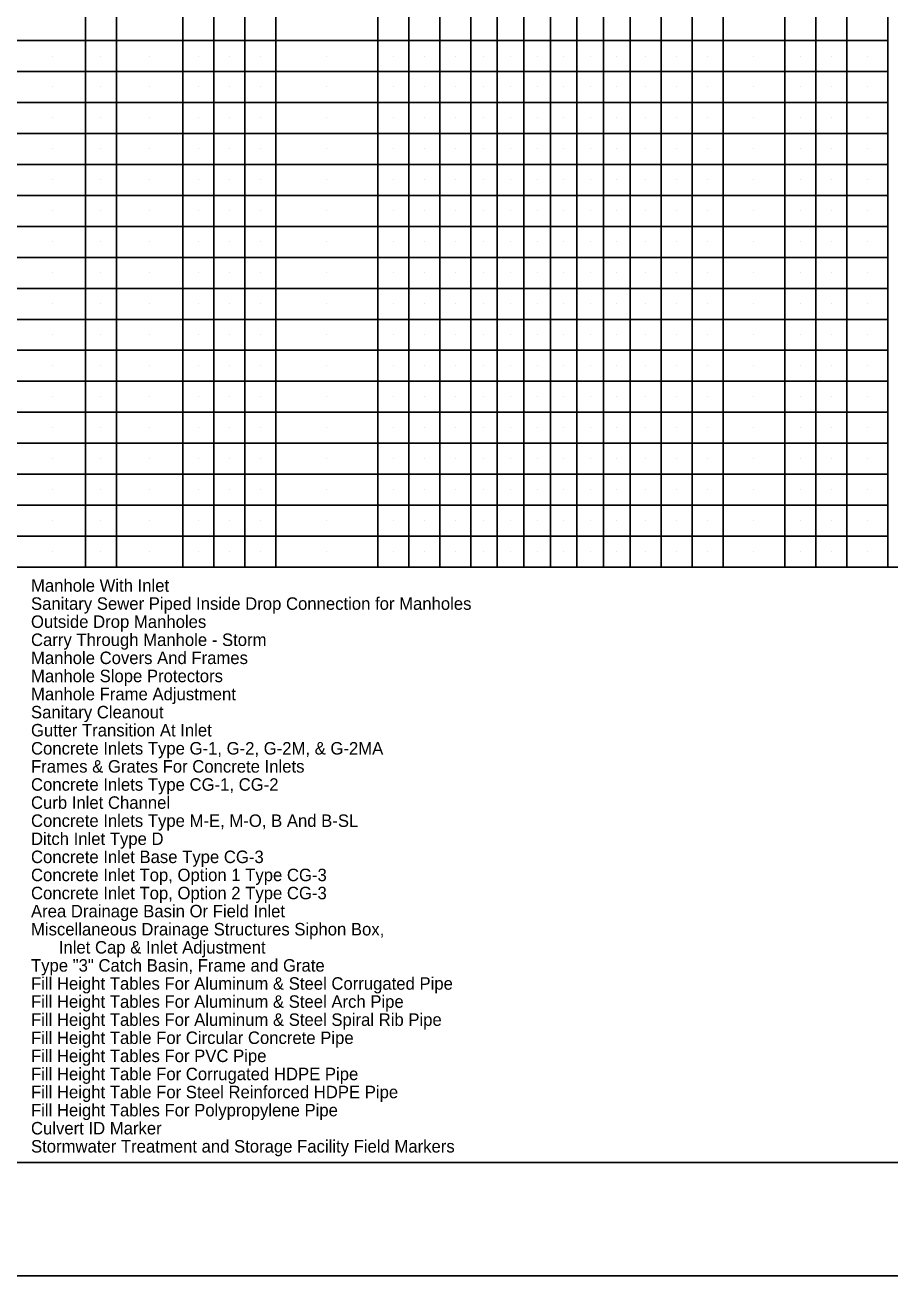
# Model space of a CAD drawing. Extents: x -1700 to 0, y 0 to 1100.
# Drawn here: x -773 to -392, y 0 to 551 of the extents above; entities that cross this region are included whole.
import ezdxf

# ---------------------------------------------------------------- set-up
doc = ezdxf.new("R2010")
doc.units = 0
for name, color, linetype in [('#plot_shape', 7, 'Continuous'), ('P_ODOT_PLAN_Border', 7, 'Continuous'), ('P_ODOT_PLAN_General', 7, 'Continuous'), ('P_RDWY_PLAN_NotesTx', 7, 'Continuous')]:
    doc.layers.add(name, color=color, linetype=linetype)

msp = doc.modelspace()

# ---------------------------------------------------------------- linework, layer by layer
at = {"layer": '#plot_shape'}
msp.add_lwpolyline([(-1700, 0), (0, 0), (0, 1100), (-1700, 1100)], close=True, dxfattribs=at)
at = {"layer": 'P_ODOT_PLAN_Border'}
msp.add_lwpolyline([(-1625, 50), (-25, 50), (-25, 1050), (-1625, 1050)], close=True, dxfattribs=at)
at = {"layer": 'P_ODOT_PLAN_General'}
for p, q in [((-392.85, 312.45), (-392.85, 1050)), ((-576.71, 312.45), (-576.71, 1036.34)), ((-506.47, 312.45), (-506.47, 1036.34)), ((-492.81, 312.45), (-492.81, 1023.66)), ((-479.15, 312.45), (-479.15, 1023.66)), ((-465.49, 312.45), (-465.49, 1023.66)), ((-438.17, 312.45), (-438.17, 1023.66)), ((-424.51, 312.45), (-424.51, 1023.66)), ((-410.85, 312.45), (-410.85, 1023.66)), ((-541.59, 312.45), (-541.59, 1010.98)), ((-662.68, 312.45), (-662.68, 998.29)), ((-565, 312.45), (-565, 998.29)), ((-553.3, 312.45), (-553.3, 998.29)), ((-529.88, 312.45), (-529.88, 998.29)), ((-518.17, 312.45), (-518.17, 998.29)), ((-732.93, 312.45), (-732.93, 985.61)), ((-690, 312.45), (-690, 985.61)), ((-617.68, 312.45), (-617.68, 985.61)), ((-604.03, 312.45), (-604.03, 985.61)), ((-746.59, 312.45), (-746.59, 973.9)), ((-703.66, 312.45), (-703.66, 973.9)), ((-676.34, 312.45), (-676.34, 973.9)), ((-590.37, 312.45), (-590.37, 973.9)), ((-392.85, 544.64), (-1033.79, 544.64)), ((-761.22, 537.81), (-761.22, 537.81)), ((-739.76, 537.81), (-739.76, 537.81)), ((-718.29, 537.81), (-718.29, 537.81)), ((-696.83, 537.81), (-696.83, 537.81)), ((-683.17, 537.81), (-683.17, 537.81)), ((-669.51, 537.81), (-669.51, 537.81)), ((-640.18, 537.81), (-640.18, 537.81)), ((-610.86, 537.81), (-610.86, 537.81)), ((-597.2, 537.81), (-597.2, 537.81)), ((-583.54, 537.81), (-583.54, 537.81)), ((-570.86, 537.81), (-570.86, 537.81)), ((-559.15, 537.81), (-559.15, 537.81)), ((-547.44, 537.81), (-547.44, 537.81)), ((-535.73, 537.81), (-535.73, 537.81)), ((-524.03, 537.81), (-524.03, 537.81)), ((-512.32, 537.81), (-512.32, 537.81)), ((-499.64, 537.81), (-499.64, 537.81)), ((-485.98, 537.81), (-485.98, 537.81)), ((-472.32, 537.81), (-472.32, 537.81)), ((-451.83, 537.81), (-451.83, 537.81)), ((-431.34, 537.81), (-431.34, 537.81)), ((-417.68, 537.81), (-417.68, 537.81)), ((-401.85, 537.81), (-401.85, 537.81)), ((-392.85, 530.98), (-1033.79, 530.98)), ((-761.22, 524.15), (-761.22, 524.15)), ((-739.76, 524.15), (-739.76, 524.15)), ((-718.29, 524.15), (-718.29, 524.15)), ((-696.83, 524.15), (-696.83, 524.15)), ((-683.17, 524.15), (-683.17, 524.15)), ((-669.51, 524.15), (-669.51, 524.15)), ((-640.18, 524.15), (-640.18, 524.15)), ((-610.86, 524.15), (-610.86, 524.15)), ((-597.2, 524.15), (-597.2, 524.15)), ((-583.54, 524.15), (-583.54, 524.15)), ((-570.86, 524.15), (-570.86, 524.15)), ((-559.15, 524.15), (-559.15, 524.15)), ((-547.44, 524.15), (-547.44, 524.15)), ((-535.73, 524.15), (-535.73, 524.15)), ((-524.03, 524.15), (-524.03, 524.15)), ((-512.32, 524.15), (-512.32, 524.15)), ((-499.64, 524.15), (-499.64, 524.15)), ((-485.98, 524.15), (-485.98, 524.15)), ((-472.32, 524.15), (-472.32, 524.15)), ((-451.83, 524.15), (-451.83, 524.15)), ((-431.34, 524.15), (-431.34, 524.15)), ((-417.68, 524.15), (-417.68, 524.15)), ((-401.85, 524.15), (-401.85, 524.15)), ((-392.85, 517.32), (-1033.79, 517.32)), ((-761.22, 510.49), (-761.22, 510.49)), ((-739.76, 510.49), (-739.76, 510.49)), ((-718.29, 510.49), (-718.29, 510.49)), ((-696.83, 510.49), (-696.83, 510.49)), ((-683.17, 510.49), (-683.17, 510.49)), ((-669.51, 510.49), (-669.51, 510.49)), ((-640.18, 510.49), (-640.18, 510.49)), ((-610.86, 510.49), (-610.86, 510.49)), ((-597.2, 510.49), (-597.2, 510.49)), ((-583.54, 510.49), (-583.54, 510.49)), ((-570.86, 510.49), (-570.86, 510.49)), ((-559.15, 510.49), (-559.15, 510.49)), ((-547.44, 510.49), (-547.44, 510.49)), ((-535.73, 510.49), (-535.73, 510.49)), ((-524.03, 510.49), (-524.03, 510.49)), ((-512.32, 510.49), (-512.32, 510.49)), ((-499.64, 510.49), (-499.64, 510.49)), ((-485.98, 510.49), (-485.98, 510.49)), ((-472.32, 510.49), (-472.32, 510.49)), ((-451.83, 510.49), (-451.83, 510.49)), ((-431.34, 510.49), (-431.34, 510.49)), ((-417.68, 510.49), (-417.68, 510.49)), ((-401.85, 510.49), (-401.85, 510.49)), ((-392.85, 503.66), (-1033.79, 503.66)), ((-761.22, 496.83), (-761.22, 496.83)), ((-739.76, 496.83), (-739.76, 496.83)), ((-718.29, 496.83), (-718.29, 496.83)), ((-696.83, 496.83), (-696.83, 496.83)), ((-683.17, 496.83), (-683.17, 496.83)), ((-669.51, 496.83), (-669.51, 496.83)), ((-640.18, 496.83), (-640.18, 496.83)), ((-610.86, 496.83), (-610.86, 496.83)), ((-597.2, 496.83), (-597.2, 496.83)), ((-583.54, 496.83), (-583.54, 496.83)), ((-570.86, 496.83), (-570.86, 496.83)), ((-559.15, 496.83), (-559.15, 496.83)), ((-547.44, 496.83), (-547.44, 496.83)), ((-535.73, 496.83), (-535.73, 496.83)), ((-524.03, 496.83), (-524.03, 496.83)), ((-512.32, 496.83), (-512.32, 496.83)), ((-499.64, 496.83), (-499.64, 496.83)), ((-485.98, 496.83), (-485.98, 496.83)), ((-472.32, 496.83), (-472.32, 496.83)), ((-451.83, 496.83), (-451.83, 496.83)), ((-431.34, 496.83), (-431.34, 496.83)), ((-417.68, 496.83), (-417.68, 496.83)), ((-401.85, 496.83), (-401.85, 496.83)), ((-392.85, 490.01), (-1033.79, 490.01)), ((-761.22, 483.18), (-761.22, 483.18)), ((-739.76, 483.18), (-739.76, 483.18)), ((-718.29, 483.18), (-718.29, 483.18)), ((-696.83, 483.18), (-696.83, 483.18)), ((-683.17, 483.18), (-683.17, 483.18)), ((-669.51, 483.18), (-669.51, 483.18)), ((-640.18, 483.18), (-640.18, 483.18)), ((-610.86, 483.18), (-610.86, 483.18)), ((-597.2, 483.18), (-597.2, 483.18)), ((-583.54, 483.18), (-583.54, 483.18)), ((-570.86, 483.18), (-570.86, 483.18)), ((-559.15, 483.18), (-559.15, 483.18)), ((-547.44, 483.18), (-547.44, 483.18)), ((-535.73, 483.18), (-535.73, 483.18)), ((-524.03, 483.18), (-524.03, 483.18)), ((-512.32, 483.18), (-512.32, 483.18)), ((-499.64, 483.18), (-499.64, 483.18)), ((-485.98, 483.18), (-485.98, 483.18)), ((-472.32, 483.18), (-472.32, 483.18)), ((-451.83, 483.18), (-451.83, 483.18)), ((-431.34, 483.18), (-431.34, 483.18)), ((-417.68, 483.18), (-417.68, 483.18)), ((-401.85, 483.18), (-401.85, 483.18)), ((-392.85, 476.35), (-1033.79, 476.35)), ((-761.22, 469.52), (-761.22, 469.52)), ((-739.76, 469.52), (-739.76, 469.52)), ((-718.29, 469.52), (-718.29, 469.52)), ((-696.83, 469.52), (-696.83, 469.52)), ((-683.17, 469.52), (-683.17, 469.52)), ((-669.51, 469.52), (-669.51, 469.52)), ((-640.18, 469.52), (-640.18, 469.52)), ((-610.86, 469.52), (-610.86, 469.52)), ((-597.2, 469.52), (-597.2, 469.52)), ((-583.54, 469.52), (-583.54, 469.52)), ((-570.86, 469.52), (-570.86, 469.52)), ((-559.15, 469.52), (-559.15, 469.52)), ((-547.44, 469.52), (-547.44, 469.52)), ((-535.73, 469.52), (-535.73, 469.52)), ((-524.03, 469.52), (-524.03, 469.52)), ((-512.32, 469.52), (-512.32, 469.52)), ((-499.64, 469.52), (-499.64, 469.52)), ((-485.98, 469.52), (-485.98, 469.52)), ((-472.32, 469.52), (-472.32, 469.52)), ((-451.83, 469.52), (-451.83, 469.52)), ((-431.34, 469.52), (-431.34, 469.52)), ((-417.68, 469.52), (-417.68, 469.52)), ((-401.85, 469.52), (-401.85, 469.52)), ((-392.85, 462.69), (-1033.79, 462.69)), ((-761.22, 455.86), (-761.22, 455.86)), ((-739.76, 455.86), (-739.76, 455.86)), ((-718.29, 455.86), (-718.29, 455.86)), ((-696.83, 455.86), (-696.83, 455.86)), ((-683.17, 455.86), (-683.17, 455.86)), ((-669.51, 455.86), (-669.51, 455.86)), ((-640.18, 455.86), (-640.18, 455.86)), ((-610.86, 455.86), (-610.86, 455.86)), ((-597.2, 455.86), (-597.2, 455.86)), ((-583.54, 455.86), (-583.54, 455.86)), ((-570.86, 455.86), (-570.86, 455.86)), ((-559.15, 455.86), (-559.15, 455.86)), ((-547.44, 455.86), (-547.44, 455.86)), ((-535.73, 455.86), (-535.73, 455.86)), ((-524.03, 455.86), (-524.03, 455.86)), ((-512.32, 455.86), (-512.32, 455.86)), ((-499.64, 455.86), (-499.64, 455.86)), ((-485.98, 455.86), (-485.98, 455.86)), ((-472.32, 455.86), (-472.32, 455.86)), ((-451.83, 455.86), (-451.83, 455.86)), ((-431.34, 455.86), (-431.34, 455.86)), ((-417.68, 455.86), (-417.68, 455.86)), ((-401.85, 455.86), (-401.85, 455.86)), ((-392.85, 449.03), (-1033.79, 449.03)), ((-761.22, 442.2), (-761.22, 442.2)), ((-739.76, 442.2), (-739.76, 442.2)), ((-718.29, 442.2), (-718.29, 442.2)), ((-696.83, 442.2), (-696.83, 442.2)), ((-683.17, 442.2), (-683.17, 442.2)), ((-669.51, 442.2), (-669.51, 442.2)), ((-640.18, 442.2), (-640.18, 442.2)), ((-610.86, 442.2), (-610.86, 442.2)), ((-597.2, 442.2), (-597.2, 442.2)), ((-583.54, 442.2), (-583.54, 442.2)), ((-570.86, 442.2), (-570.86, 442.2)), ((-559.15, 442.2), (-559.15, 442.2)), ((-547.44, 442.2), (-547.44, 442.2)), ((-535.73, 442.2), (-535.73, 442.2)), ((-524.03, 442.2), (-524.03, 442.2)), ((-512.32, 442.2), (-512.32, 442.2)), ((-499.64, 442.2), (-499.64, 442.2)), ((-485.98, 442.2), (-485.98, 442.2)), ((-472.32, 442.2), (-472.32, 442.2)), ((-451.83, 442.2), (-451.83, 442.2)), ((-431.34, 442.2), (-431.34, 442.2)), ((-417.68, 442.2), (-417.68, 442.2)), ((-401.85, 442.2), (-401.85, 442.2)), ((-392.85, 435.37), (-1033.79, 435.37)), ((-761.22, 428.54), (-761.22, 428.54)), ((-739.76, 428.54), (-739.76, 428.54)), ((-718.29, 428.54), (-718.29, 428.54)), ((-696.83, 428.54), (-696.83, 428.54)), ((-683.17, 428.54), (-683.17, 428.54)), ((-669.51, 428.54), (-669.51, 428.54)), ((-640.18, 428.54), (-640.18, 428.54)), ((-610.86, 428.54), (-610.86, 428.54)), ((-597.2, 428.54), (-597.2, 428.54)), ((-583.54, 428.54), (-583.54, 428.54)), ((-570.86, 428.54), (-570.86, 428.54)), ((-559.15, 428.54), (-559.15, 428.54)), ((-547.44, 428.54), (-547.44, 428.54)), ((-535.73, 428.54), (-535.73, 428.54)), ((-524.03, 428.54), (-524.03, 428.54)), ((-512.32, 428.54), (-512.32, 428.54)), ((-499.64, 428.54), (-499.64, 428.54)), ((-485.98, 428.54), (-485.98, 428.54)), ((-472.32, 428.54), (-472.32, 428.54)), ((-451.83, 428.54), (-451.83, 428.54)), ((-431.34, 428.54), (-431.34, 428.54)), ((-417.68, 428.54), (-417.68, 428.54)), ((-401.85, 428.54), (-401.85, 428.54)), ((-392.85, 421.71), (-1033.79, 421.71)), ((-761.22, 414.88), (-761.22, 414.88)), ((-739.76, 414.88), (-739.76, 414.88)), ((-718.29, 414.88), (-718.29, 414.88)), ((-696.83, 414.88), (-696.83, 414.88)), ((-683.17, 414.88), (-683.17, 414.88)), ((-669.51, 414.88), (-669.51, 414.88)), ((-640.18, 414.88), (-640.18, 414.88)), ((-610.86, 414.88), (-610.86, 414.88)), ((-597.2, 414.88), (-597.2, 414.88)), ((-583.54, 414.88), (-583.54, 414.88)), ((-570.86, 414.88), (-570.86, 414.88)), ((-559.15, 414.88), (-559.15, 414.88)), ((-547.44, 414.88), (-547.44, 414.88)), ((-535.73, 414.88), (-535.73, 414.88)), ((-524.03, 414.88), (-524.03, 414.88)), ((-512.32, 414.88), (-512.32, 414.88)), ((-499.64, 414.88), (-499.64, 414.88)), ((-485.98, 414.88), (-485.98, 414.88)), ((-472.32, 414.88), (-472.32, 414.88)), ((-451.83, 414.88), (-451.83, 414.88)), ((-431.34, 414.88), (-431.34, 414.88)), ((-417.68, 414.88), (-417.68, 414.88)), ((-401.85, 414.88), (-401.85, 414.88)), ((-392.85, 408.06), (-1033.79, 408.06)), ((-761.22, 401.23), (-761.22, 401.23)), ((-739.76, 401.23), (-739.76, 401.23)), ((-718.29, 401.23), (-718.29, 401.23)), ((-696.83, 401.23), (-696.83, 401.23)), ((-683.17, 401.23), (-683.17, 401.23)), ((-669.51, 401.23), (-669.51, 401.23)), ((-640.18, 401.23), (-640.18, 401.23)), ((-610.86, 401.23), (-610.86, 401.23)), ((-597.2, 401.23), (-597.2, 401.23)), ((-583.54, 401.23), (-583.54, 401.23)), ((-570.86, 401.23), (-570.86, 401.23)), ((-559.15, 401.23), (-559.15, 401.23)), ((-547.44, 401.23), (-547.44, 401.23)), ((-535.73, 401.23), (-535.73, 401.23)), ((-524.03, 401.23), (-524.03, 401.23)), ((-512.32, 401.23), (-512.32, 401.23)), ((-499.64, 401.23), (-499.64, 401.23)), ((-485.98, 401.23), (-485.98, 401.23)), ((-472.32, 401.23), (-472.32, 401.23)), ((-451.83, 401.23), (-451.83, 401.23)), ((-431.34, 401.23), (-431.34, 401.23)), ((-417.68, 401.23), (-417.68, 401.23)), ((-401.85, 401.23), (-401.85, 401.23)), ((-392.85, 394.4), (-1033.79, 394.4)), ((-761.22, 387.57), (-761.22, 387.57)), ((-739.76, 387.57), (-739.76, 387.57)), ((-718.29, 387.57), (-718.29, 387.57)), ((-696.83, 387.57), (-696.83, 387.57)), ((-683.17, 387.57), (-683.17, 387.57)), ((-669.51, 387.57), (-669.51, 387.57)), ((-640.18, 387.57), (-640.18, 387.57)), ((-610.86, 387.57), (-610.86, 387.57)), ((-597.2, 387.57), (-597.2, 387.57)), ((-583.54, 387.57), (-583.54, 387.57)), ((-570.86, 387.57), (-570.86, 387.57)), ((-559.15, 387.57), (-559.15, 387.57)), ((-547.44, 387.57), (-547.44, 387.57)), ((-535.73, 387.57), (-535.73, 387.57)), ((-524.03, 387.57), (-524.03, 387.57)), ((-512.32, 387.57), (-512.32, 387.57)), ((-499.64, 387.57), (-499.64, 387.57)), ((-485.98, 387.57), (-485.98, 387.57)), ((-472.32, 387.57), (-472.32, 387.57)), ((-451.83, 387.57), (-451.83, 387.57)), ((-431.34, 387.57), (-431.34, 387.57)), ((-417.68, 387.57), (-417.68, 387.57)), ((-401.85, 387.57), (-401.85, 387.57)), ((-392.85, 380.74), (-1033.79, 380.74)), ((-761.22, 373.91), (-761.22, 373.91)), ((-739.76, 373.91), (-739.76, 373.91)), ((-718.29, 373.91), (-718.29, 373.91)), ((-696.83, 373.91), (-696.83, 373.91)), ((-683.17, 373.91), (-683.17, 373.91)), ((-669.51, 373.91), (-669.51, 373.91)), ((-640.18, 373.91), (-640.18, 373.91)), ((-610.86, 373.91), (-610.86, 373.91)), ((-597.2, 373.91), (-597.2, 373.91)), ((-583.54, 373.91), (-583.54, 373.91)), ((-570.86, 373.91), (-570.86, 373.91)), ((-559.15, 373.91), (-559.15, 373.91)), ((-547.44, 373.91), (-547.44, 373.91)), ((-535.73, 373.91), (-535.73, 373.91)), ((-524.03, 373.91), (-524.03, 373.91)), ((-512.32, 373.91), (-512.32, 373.91)), ((-499.64, 373.91), (-499.64, 373.91)), ((-485.98, 373.91), (-485.98, 373.91)), ((-472.32, 373.91), (-472.32, 373.91)), ((-451.83, 373.91), (-451.83, 373.91)), ((-431.34, 373.91), (-431.34, 373.91)), ((-417.68, 373.91), (-417.68, 373.91)), ((-401.85, 373.91), (-401.85, 373.91)), ((-392.85, 367.08), (-1033.79, 367.08)), ((-761.22, 360.25), (-761.22, 360.25)), ((-739.76, 360.25), (-739.76, 360.25)), ((-718.29, 360.25), (-718.29, 360.25)), ((-696.83, 360.25), (-696.83, 360.25)), ((-683.17, 360.25), (-683.17, 360.25)), ((-669.51, 360.25), (-669.51, 360.25)), ((-640.18, 360.25), (-640.18, 360.25)), ((-610.86, 360.25), (-610.86, 360.25)), ((-597.2, 360.25), (-597.2, 360.25)), ((-583.54, 360.25), (-583.54, 360.25)), ((-570.86, 360.25), (-570.86, 360.25)), ((-559.15, 360.25), (-559.15, 360.25)), ((-547.44, 360.25), (-547.44, 360.25)), ((-535.73, 360.25), (-535.73, 360.25)), ((-524.03, 360.25), (-524.03, 360.25)), ((-512.32, 360.25), (-512.32, 360.25)), ((-499.64, 360.25), (-499.64, 360.25)), ((-485.98, 360.25), (-485.98, 360.25)), ((-472.32, 360.25), (-472.32, 360.25)), ((-451.83, 360.25), (-451.83, 360.25)), ((-431.34, 360.25), (-431.34, 360.25)), ((-417.68, 360.25), (-417.68, 360.25)), ((-401.85, 360.25), (-401.85, 360.25)), ((-392.85, 353.42), (-1033.79, 353.42)), ((-761.22, 346.59), (-761.22, 346.59)), ((-739.76, 346.59), (-739.76, 346.59)), ((-718.29, 346.59), (-718.29, 346.59)), ((-696.83, 346.59), (-696.83, 346.59)), ((-683.17, 346.59), (-683.17, 346.59)), ((-669.51, 346.59), (-669.51, 346.59)), ((-640.18, 346.59), (-640.18, 346.59)), ((-610.86, 346.59), (-610.86, 346.59)), ((-597.2, 346.59), (-597.2, 346.59)), ((-583.54, 346.59), (-583.54, 346.59)), ((-570.86, 346.59), (-570.86, 346.59)), ((-559.15, 346.59), (-559.15, 346.59)), ((-547.44, 346.59), (-547.44, 346.59)), ((-535.73, 346.59), (-535.73, 346.59)), ((-524.03, 346.59), (-524.03, 346.59)), ((-512.32, 346.59), (-512.32, 346.59)), ((-499.64, 346.59), (-499.64, 346.59)), ((-485.98, 346.59), (-485.98, 346.59)), ((-472.32, 346.59), (-472.32, 346.59)), ((-451.83, 346.59), (-451.83, 346.59)), ((-431.34, 346.59), (-431.34, 346.59)), ((-417.68, 346.59), (-417.68, 346.59)), ((-401.85, 346.59), (-401.85, 346.59)), ((-392.85, 339.76), (-1033.79, 339.76)), ((-761.22, 332.93), (-761.22, 332.93)), ((-739.76, 332.93), (-739.76, 332.93)), ((-718.29, 332.93), (-718.29, 332.93)), ((-696.83, 332.93), (-696.83, 332.93)), ((-683.17, 332.93), (-683.17, 332.93)), ((-669.51, 332.93), (-669.51, 332.93)), ((-640.18, 332.93), (-640.18, 332.93)), ((-610.86, 332.93), (-610.86, 332.93)), ((-597.2, 332.93), (-597.2, 332.93)), ((-583.54, 332.93), (-583.54, 332.93)), ((-570.86, 332.93), (-570.86, 332.93)), ((-559.15, 332.93), (-559.15, 332.93)), ((-547.44, 332.93), (-547.44, 332.93)), ((-535.73, 332.93), (-535.73, 332.93)), ((-524.03, 332.93), (-524.03, 332.93)), ((-512.32, 332.93), (-512.32, 332.93)), ((-499.64, 332.93), (-499.64, 332.93)), ((-485.98, 332.93), (-485.98, 332.93)), ((-472.32, 332.93), (-472.32, 332.93)), ((-451.83, 332.93), (-451.83, 332.93)), ((-431.34, 332.93), (-431.34, 332.93)), ((-417.68, 332.93), (-417.68, 332.93)), ((-401.85, 332.93), (-401.85, 332.93)), ((-392.85, 326.1), (-1033.79, 326.1)), ((-761.22, 319.28), (-761.22, 319.28)), ((-739.76, 319.28), (-739.76, 319.28)), ((-718.29, 319.28), (-718.29, 319.28)), ((-696.83, 319.28), (-696.83, 319.28)), ((-683.17, 319.28), (-683.17, 319.28)), ((-669.51, 319.28), (-669.51, 319.28)), ((-640.18, 319.28), (-640.18, 319.28)), ((-610.86, 319.28), (-610.86, 319.28)), ((-597.2, 319.28), (-597.2, 319.28)), ((-583.54, 319.28), (-583.54, 319.28)), ((-570.86, 319.28), (-570.86, 319.28)), ((-559.15, 319.28), (-559.15, 319.28)), ((-547.44, 319.28), (-547.44, 319.28)), ((-535.73, 319.28), (-535.73, 319.28)), ((-524.03, 319.28), (-524.03, 319.28)), ((-512.32, 319.28), (-512.32, 319.28)), ((-499.64, 319.28), (-499.64, 319.28)), ((-485.98, 319.28), (-485.98, 319.28)), ((-472.32, 319.28), (-472.32, 319.28)), ((-451.83, 319.28), (-451.83, 319.28)), ((-431.34, 319.28), (-431.34, 319.28)), ((-417.68, 319.28), (-417.68, 319.28)), ((-401.85, 319.28), (-401.85, 319.28)), ((-25.02, 312.45), (-1625, 312.45))]:
    msp.add_line(p, q, dxfattribs=at)

# ---------------------------------------------------------------- texts
at = {"layer": 'P_RDWY_PLAN_NotesTx'}
for s, p in [('Manhole With Inlet', (-770.57, 301.65)), ('Sanitary Sewer Piped Inside Drop Connection for Manholes', (-770.57, 293.67)), ('Outside Drop Manholes', (-770.57, 285.7)), ('Carry Through Manhole - Storm', (-770.57, 277.72)), ('Manhole Covers And Frames', (-770.57, 269.75)), ('Manhole Slope Protectors', (-770.57, 261.77)), ('Manhole Frame Adjustment', (-770.57, 253.8)), ('Sanitary Cleanout', (-770.57, 245.82)), ('Gutter Transition At Inlet', (-770.57, 237.85)), ('Concrete Inlets Type G-1, G-2, G-2M, & G-2MA', (-770.57, 229.87)), ('Frames & Grates For Concrete Inlets', (-770.57, 221.9)), ('Concrete Inlets Type CG-1, CG-2', (-770.57, 213.92)), ('Curb Inlet Channel', (-770.57, 205.95)), ('Concrete Inlets Type M-E, M-O, B And B-SL', (-770.57, 197.97)), ('Ditch Inlet Type D', (-770.57, 190)), ('Concrete Inlet Base Type CG-3', (-770.57, 182.02)), ('Concrete Inlet Top, Option 1 Type CG-3', (-770.57, 174.05)), ('Concrete Inlet Top, Option 2 Type CG-3', (-770.57, 166.07)), ('Area Drainage Basin Or Field Inlet', (-770.57, 158.1)), ('Miscellaneous Drainage Structures Siphon Box,', (-770.57, 150.12)), ('      Inlet Cap & Inlet Adjustment', (-770.57, 142.15)), ('Type "3" Catch Basin, Frame and Grate', (-770.57, 134.17)), ('Fill Height Tables For Aluminum & Steel Corrugated Pipe', (-770.57, 126.2)), ('Fill Height Tables For Aluminum & Steel Arch Pipe', (-770.57, 118.22)), ('Fill Height Tables For Aluminum & Steel Spiral Rib Pipe ', (-770.57, 110.25)), ('Fill Height Table For Circular Concrete Pipe', (-770.57, 102.27)), ('Fill Height Tables For PVC Pipe ', (-770.57, 94.3)), ('Fill Height Table For Corrugated HDPE Pipe', (-770.57, 86.32)), ('Fill Height Table For Steel Reinforced HDPE Pipe', (-770.57, 78.35)), ('Fill Height Tables For Polypropylene Pipe', (-770.57, 70.37)), ('Culvert ID Marker', (-770.57, 62.4)), ('Stormwater Treatment and Storage Facility Field Markers', (-770.57, 54.42))]:
    msp.add_text(s, height=5.5, dxfattribs=at).set_placement(p)

doc.saveas('drawing.dxf')
